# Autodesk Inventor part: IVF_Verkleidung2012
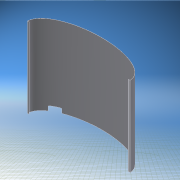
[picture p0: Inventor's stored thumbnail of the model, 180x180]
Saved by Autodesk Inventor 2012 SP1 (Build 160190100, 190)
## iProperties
Created: 2012-01
Part Number: IVF_Verkleidung2012
Material: Edelstahl
Document SubType Name: Blech
Designer: Stefan
Mass: 6103.42 g
Surface Area: 15149.2 cm^2
Volume: 755.374 cm^3
Density: 8.08 g/cm^3
Sheet Metal Rule: Standard
Sheet Metal Width: 700,000 mm
Sheet Metal Length: 1089,067 mm
Sheet Metal Area: 762346,964 mm^2
Flat Pattern Width: 70 cm
Flat Pattern Length: 108.907 cm
Flat Pattern Area: 7623.47 cm^2
Author: Stefan
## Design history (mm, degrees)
sketch "Skizze1"
  geometry: L1 (-435, 0)-(-451, 0) reference; L2 (435, 0)-(451, 0) reference; 2 further points; 1 other entity
  constraints: 4 end point, 2 horizontal, 10 other
feature "Extrusionsfläche1" sketch "Skizze1" dims "d20" = 700, "d21" = 0
fillet "Rundung3" dims "d22" = 2 (= Biegeradius + Stärke)
feature "Verdickung1" dims "d23" = 1 (= Stärke), "d24" = 1 (= Stärke)
sketch "Skizze2"
  geometry: L1 (116, -310)-(144, -310) reference; L2 (150, -316)-(150, -344) reference; L3 (110, -344)-(110, -316) reference; L4 (116, -310)-(144, -310); L5 (150, -316)-(150, -355.272); L6 (150, -355.272)-(110, -355.272); L7 (110, -355.272)-(110, -316); A1 r 6 centre (116, -316) between (116, -310) and (110, -316); A2 r 6 centre (144, -316) between (150, -316) and (144, -310); 1 further point
  constraints: 8 end point, 4 point on circle, 3 perpendicular, 2 centre point, 1 collinear, 2 other
feature "Ausklinkung1" sketch "Skizze2" dims "d16" = 1 (= Stärke), "d17" = 0
feature "Verdickung2" dims "d25" = 1 (= Stärke), "d26" = 1 (= Stärke)
feature "Verdickung3" dims "d27" = 1 (= Stärke), "d28" = 1 (= Stärke)
node "Volumenkörper1"
node "Referenz1"
node "Referenz2"
node "Referenz3"
node "Referenz4"
node "Referenz5"
node "Flächen1"
feature "Definition1"
other parameters: "Stärke" = 1 (derived), "KFaktor" = 4.4, "Biegeradius" = 1 (= Stärke), "BreiteBiegungsfreistellung" = 1 (= Stärke), "TiefeBiegungsfreistellung" = 0.5 (= 0.5 x Stärke), "GrößeEckenfreistellung" = 4 (= 4 x Stärke), "AbstandVerbindung" = 0.01, "MinimalRest" = 2 (= 2 x Stärke), "Übergangsradius" = 1 (= Biegeradius), "JacobiRadiusGröße" = 1 (= Biegeradius), "Abstandsgröße" = 1 (= Stärke), "Abstandsgröße" = 1, "Biegeradius" = 1, "BreiteBiegungsfreistellung" = 1, "GrößeEckenfreistellung" = 4, "JacobiRadiusGröße" = 1, "MinimalRest" = 2, "Stärke" = 1, "TiefeBiegungsfreistellung" = 0.5, "Übergangsradius" = 1
